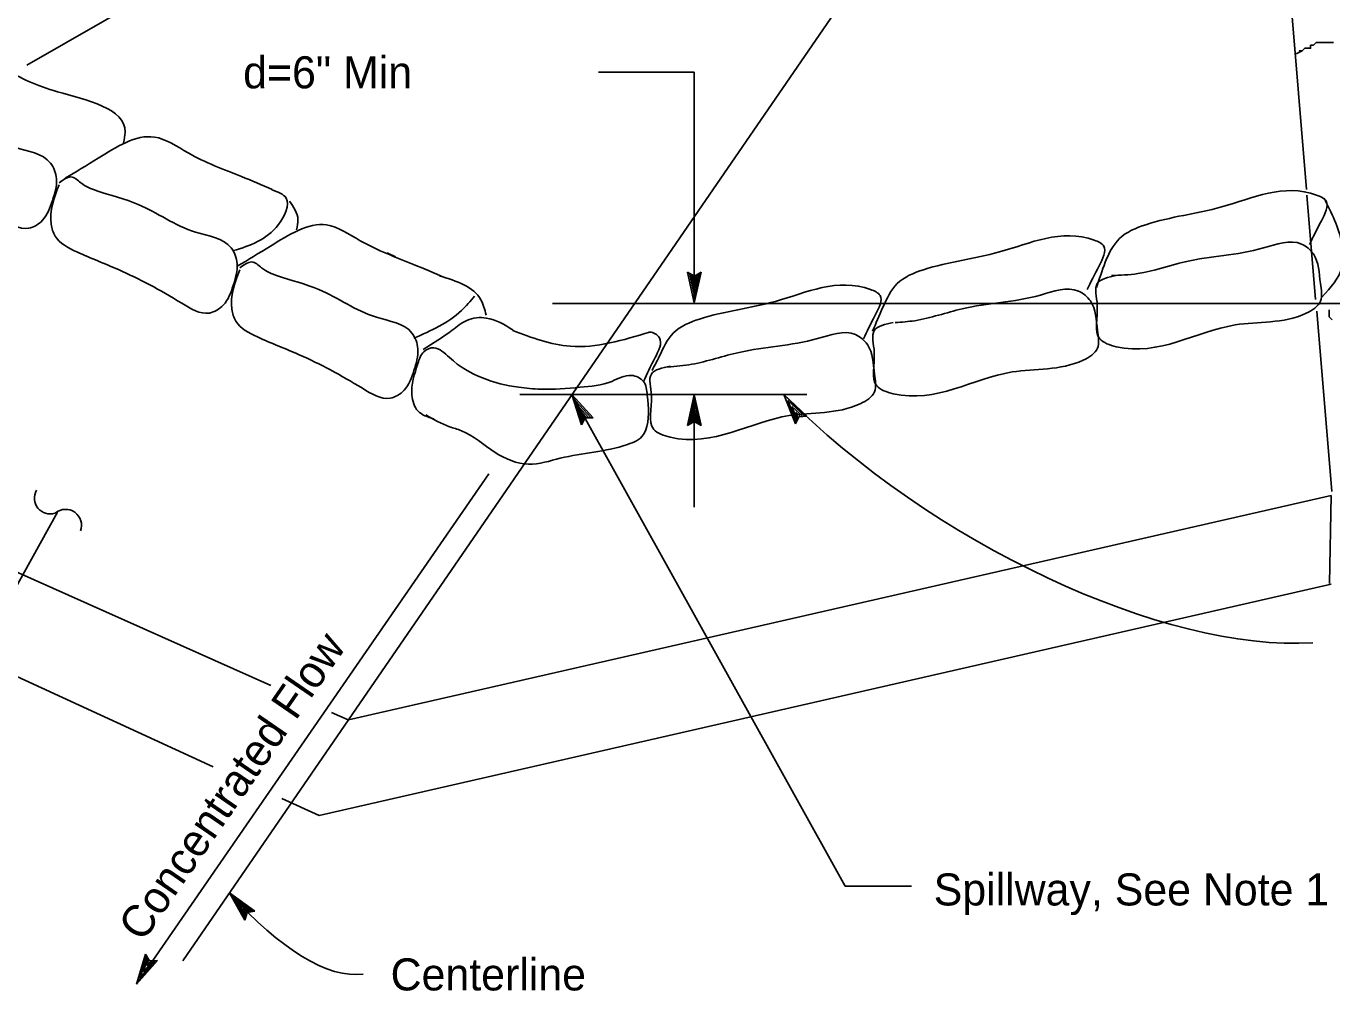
# Model space of a CAD drawing. Extents: x 6707415 to 6708768, y 1869893 to 1870831.
# Drawn here: x 6708364.3 to 6708608.7, y 1870111.8 to 1870292.4 of the extents above; entities that cross this region are included whole.
import ezdxf

# ---------------------------------------------------------------- set-up
doc = ezdxf.new("R2010")
doc.units = 0
for name, color, linetype in [('56 Stg 3 Anno', 7, 'Continuous'), ('57 Undefined', 7, 'Continuous'), ('60 Nongeo Data', 7, 'Continuous')]:
    doc.layers.add(name, color=color, linetype=linetype)

msp = doc.modelspace()

# ---------------------------------------------------------------- linework, layer by layer
at = {"layer": '56 Stg 3 Anno'}
for p, q in [((6708393.6, 1870117.38), (6708574.91, 1870381.27)), ((6708489.35, 1870283.77), (6708471.41, 1870283.77)), ((6708489.35, 1870240.61), (6708489.35, 1870283.77)), ((6708489.35, 1870240.61), (6708488.1, 1870246.37)), ((6708488.1, 1870246.37), (6708488.1, 1870246.37)), ((6708488.1, 1870246.37), (6708489.37, 1870245.6)), ((6708489.36, 1870241.94), (6708488.44, 1870246.15)), ((6708489.37, 1870243.26), (6708488.78, 1870245.98)), ((6708489.37, 1870244.59), (6708489.12, 1870245.75)), ((6708490.66, 1870246.36), (6708489.35, 1870240.61)), ((6708490.32, 1870246.16), (6708489.36, 1870241.93)), ((6708489.37, 1870245.6), (6708490.66, 1870246.36)), ((6708489.97, 1870245.93), (6708489.37, 1870243.26)), ((6708489.64, 1870245.77), (6708489.37, 1870244.59)), ((6708490.66, 1870246.36), (6708490.66, 1870246.36)), ((6708489.35, 1870240.61), (6708489.35, 1870240.61)), ((6708641.41, 1870240.47), (6708462.78, 1870240.47)), ((6708510.4, 1870223.41), (6708456.68, 1870223.41)), ((6708466.45, 1870223.41), (6708517.58, 1870131.35)), ((6708468.21, 1870217.77), (6708466.45, 1870223.41)), ((6708466.45, 1870223.41), (6708466.45, 1870223.41)), ((6708466.45, 1870223.41), (6708470.43, 1870219.05)), ((6708468.4, 1870218.12), (6708467.11, 1870222.26)), ((6708467.12, 1870222.25), (6708470.02, 1870219.08)), ((6708468.59, 1870218.49), (6708467.77, 1870221.11)), ((6708467.77, 1870221.11), (6708469.64, 1870219.06)), ((6708488.06, 1870217.63), (6708489.35, 1870223.39)), ((6708488.4, 1870217.84), (6708489.35, 1870222.07)), ((6708489.35, 1870223.39), (6708489.35, 1870223.39)), ((6708489.35, 1870223.39), (6708490.62, 1870217.63)), ((6708489.35, 1870202.31), (6708489.35, 1870223.39)), ((6708489.36, 1870222.06), (6708490.28, 1870217.86)), ((6708508.31, 1870217.92), (6708506.13, 1870223.41)), ((6708506.13, 1870223.41), (6708506.13, 1870223.41)), ((6708506.13, 1870223.41), (6708510.43, 1870219.36)), ((6708508.47, 1870218.28), (6708506.88, 1870222.31)), ((6708506.89, 1870222.3), (6708510.01, 1870219.35)), ((6708508.63, 1870218.66), (6708507.62, 1870221.21)), ((6708507.62, 1870221.21), (6708509.64, 1870219.3)), ((6708468.94, 1870219.08), (6708468.21, 1870217.77)), ((6708468.79, 1870218.8), (6708468.43, 1870219.96)), ((6708468.43, 1870219.96), (6708469.23, 1870219.08)), ((6708470.43, 1870219.05), (6708468.94, 1870219.08)), ((6708470.43, 1870219.05), (6708470.43, 1870219.05)), ((6708488.75, 1870218.06), (6708489.35, 1870220.74)), ((6708489.08, 1870218.23), (6708489.35, 1870219.41)), ((6708489.35, 1870220.74), (6708489.95, 1870218.03)), ((6708489.35, 1870219.41), (6708489.6, 1870218.25)), ((6708508.94, 1870219.28), (6708508.31, 1870217.92)), ((6708508.81, 1870218.99), (6708508.37, 1870220.11)), ((6708508.37, 1870220.11), (6708509.23, 1870219.3)), ((6708510.43, 1870219.36), (6708508.94, 1870219.28)), ((6708510.43, 1870219.36), (6708510.43, 1870219.36)), ((6708468.21, 1870217.77), (6708468.21, 1870217.77)), ((6708489.35, 1870218.4), (6708488.06, 1870217.63)), ((6708488.06, 1870217.63), (6708488.06, 1870217.63)), ((6708490.62, 1870217.63), (6708489.35, 1870218.4)), ((6708490.62, 1870217.63), (6708490.62, 1870217.63)), ((6708508.31, 1870217.92), (6708508.31, 1870217.92)), ((6708384.97, 1870112.98), (6708450.88, 1870208.6)), ((6708370.17, 1870201.4), (6708341.72, 1870150.18)), ((6708530.03, 1870131.34), (6708517.58, 1870131.35)), ((6708405.21, 1870124.98), (6708402.33, 1870130.13)), ((6708402.33, 1870130.13), (6708402.33, 1870130.13)), ((6708402.33, 1870130.13), (6708407.12, 1870126.68)), ((6708405.33, 1870125.36), (6708403.21, 1870129.14)), ((6708403.23, 1870129.14), (6708406.71, 1870126.62)), ((6708405.43, 1870125.76), (6708404.1, 1870128.15)), ((6708404.1, 1870128.15), (6708406.35, 1870126.53)), ((6708405.57, 1870126.1), (6708404.98, 1870127.16)), ((6708404.98, 1870127.16), (6708405.95, 1870126.47)), ((6708405.66, 1870126.41), (6708405.21, 1870124.98)), ((6708407.12, 1870126.68), (6708405.66, 1870126.41)), ((6708407.12, 1870126.68), (6708407.12, 1870126.68)), ((6708405.21, 1870124.98), (6708405.21, 1870124.98)), ((6708384.97, 1870112.98), (6708386.6, 1870118.65)), ((6708386.6, 1870118.65), (6708386.6, 1870118.65)), ((6708386.6, 1870118.65), (6708387.36, 1870117.37)), ((6708388.85, 1870117.43), (6708384.97, 1870112.98)), ((6708388.45, 1870117.41), (6708385.6, 1870114.14)), ((6708385.61, 1870114.16), (6708386.8, 1870118.29)), ((6708386.24, 1870115.31), (6708387.01, 1870117.98)), ((6708388.04, 1870117.37), (6708386.24, 1870115.31)), ((6708386.87, 1870116.47), (6708387.2, 1870117.62)), ((6708387.67, 1870117.38), (6708386.87, 1870116.47)), ((6708387.36, 1870117.37), (6708388.85, 1870117.43)), ((6708388.85, 1870117.43), (6708388.85, 1870117.43)), ((6708384.97, 1870112.98), (6708384.97, 1870112.98))]:
    msp.add_line(p, q, dxfattribs=at)
for centre, radius, start, end in [((6708368.79, 1870204.02), 2.96, 150.2525, 287.0948), ((6708371.66, 1870198.94), 2.99, 339.2494, 129.7493)]:
    msp.add_arc(centre, radius, start, end, dxfattribs=at)
for centre, major_axis, ratio, start_param, end_param in [((6708556.07, 1870228.58), (68.84, -42.22), 0.434429, 4.196151, 5.732815), ((6708401.15, 1870176.64), (-29.01, 60.95), 0.360833, 2.25187, 3.024453)]:
    msp.add_ellipse(centre, major_axis=major_axis, ratio=ratio, start_param=start_param, end_param=end_param, dxfattribs=at)
at = {"layer": '60 Nongeo Data'}
for p, q in [((6708364.4, 1870285.1), (6708457.05, 1870338.34)), ((6708603.97, 1870261.83), (6708598.97, 1870322.05)), ((6708605.65, 1870241.24), (6708604.03, 1870260.77)), ((6708431.89, 1870249.98), (6708433.44, 1870249.23)), ((6708608.67, 1870205.28), (6708605.86, 1870239.03)), ((6708410.09, 1870168.95), (6708270.51, 1870231.15)), ((6708608.54, 1870204.55), (6708608.26, 1870188.04)), ((6708424.54, 1870162.51), (6708421.47, 1870163.87))]:
    msp.add_line(p, q, dxfattribs=at)
for points in [[(6708602.03, 1870287.23), (6708603.1, 1870287.76), (6708602.57, 1870287.76), (6708603.1, 1870287.76), (6708603.64, 1870288.29), (6708604.17, 1870288.29), (6708604.71, 1870288.29), (6708604.71, 1870288.83), (6708605.24, 1870288.83), (6708605.78, 1870289.36), (6708606.31, 1870289.36), (6708607.38, 1870289.36), (6708608.99, 1870289.36)], [(6708608.74, 1870237.44), (6708608.2, 1870237.98), (6708608.2, 1870238.51), (6708608.2, 1870239.05), (6708608.2, 1870239.26)], [(6708399.28, 1870153.7), (6708268.39, 1870213.92)], [(6708424.62, 1870162.52), (6708608.54, 1870204.55)], [(6708608.53, 1870187.89), (6708419.11, 1870144.57), (6708412.12, 1870147.79)]]:
    msp.add_lwpolyline(points, dxfattribs=at)
for points in [[(6708337.24, 1870279.53), (6708348.66, 1870286.04), (6708353.85, 1870287.52), (6708360.14, 1870284.57), (6708370.14, 1870280.13), (6708382.81, 1870272.53), (6708382.5, 1870270.58)], [(6708336.62, 1870278.61), (6708335.13, 1870271.21), (6708335.88, 1870269), (6708339.95, 1870266.04), (6708347.73, 1870262.71), (6708359.58, 1870256.43), (6708364.76, 1870254.58), (6708367.35, 1870256.06), (6708369.21, 1870259.76), (6708369.95, 1870263.82), (6708368.84, 1870266.78), (6708362.17, 1870269.74), (6708351.43, 1870274.91), (6708343.65, 1870277.5), (6708340.69, 1870278.98), (6708338.84, 1870280.08), (6708337.73, 1870279.71), (6708336.62, 1870278.98)], [(6708371.57, 1870263.92), (6708377.77, 1870267.67), (6708388.3, 1870271.65), (6708394.59, 1870268.69), (6708404.59, 1870264.26), (6708410.34, 1870261.83)], [(6708370.45, 1870262.71), (6708368.97, 1870255.32), (6708369.71, 1870253.1), (6708373.78, 1870250.15), (6708381.56, 1870246.82), (6708393.41, 1870240.54), (6708398.6, 1870238.69), (6708401.19, 1870240.17), (6708403.04, 1870243.86), (6708403.78, 1870247.93), (6708402.67, 1870250.89), (6708396, 1870253.84), (6708385.26, 1870259.02), (6708377.49, 1870261.6), (6708374.52, 1870263.08), (6708372.67, 1870264.19), (6708371.56, 1870263.82), (6708370.45, 1870263.08)], [(6708604.5, 1870251.53), (6708606.72, 1870255.97), (6708607.61, 1870259.66), (6708605.84, 1870260.77), (6708588.06, 1870258.55), (6708573.84, 1870255.23), (6708568.95, 1870252.64), (6708566.28, 1870248.2), (6708564.66, 1870243.47)], [(6708403.11, 1870250.37), (6708411.5, 1870255.25), (6708412.95, 1870260.22), (6708410.26, 1870261.77)], [(6708607.24, 1870260.19), (6708610.57, 1870251.69), (6708610.57, 1870247.25), (6708606.87, 1870241.71)], [(6708413.6, 1870259.63), (6708415.17, 1870256.21), (6708414.87, 1870254.25)], [(6708403.8, 1870247.45), (6708410, 1870251.21), (6708420.53, 1870255.18), (6708426.82, 1870252.23), (6708436.82, 1870247.79), (6708442.57, 1870245.36)], [(6708562.89, 1870243.09), (6708565.11, 1870247.53), (6708566, 1870251.23), (6708564.22, 1870252.33), (6708546.45, 1870250.12), (6708532.23, 1870246.79), (6708527.34, 1870244.2), (6708524.67, 1870239.77), (6708522.69, 1870235.27)], [(6708568.34, 1870245.7), (6708564.78, 1870244.22), (6708564.78, 1870240.15), (6708565.23, 1870233.87), (6708568.34, 1870232.39), (6708590.56, 1870236.46), (6708603.89, 1870238.67), (6708606.55, 1870240.89), (6708606.55, 1870244.22), (6708605.22, 1870249.76), (6708603, 1870251.61), (6708595.89, 1870250.87), (6708581.22, 1870248.28), (6708572.34, 1870246.07), (6708567.45, 1870245.7)], [(6708404.28, 1870246.78), (6708402.8, 1870239.39), (6708403.54, 1870237.17), (6708407.62, 1870234.21), (6708415.39, 1870230.88), (6708427.24, 1870224.6), (6708432.43, 1870222.75), (6708435.02, 1870224.23), (6708436.87, 1870227.93), (6708437.61, 1870231.99), (6708436.5, 1870234.95), (6708429.84, 1870237.91), (6708419.1, 1870243.08), (6708411.32, 1870245.67), (6708408.36, 1870247.15), (6708406.51, 1870248.26), (6708405.39, 1870247.89), (6708404.28, 1870247.15)], [(6708441.68, 1870245.66), (6708449.4, 1870241.18), (6708450.37, 1870238.32)], [(6708521, 1870233.86), (6708523.23, 1870238.3), (6708524.12, 1870241.99), (6708522.34, 1870243.1), (6708504.56, 1870240.88), (6708490.34, 1870237.56), (6708485.45, 1870234.97), (6708482.79, 1870230.54), (6708481.45, 1870227.95)], [(6708526.6, 1870236.89), (6708523.04, 1870235.41), (6708523.04, 1870231.34), (6708523.49, 1870225.06), (6708526.6, 1870223.58), (6708548.82, 1870227.65), (6708562.15, 1870229.87), (6708564.82, 1870232.08), (6708564.82, 1870235.41), (6708563.49, 1870240.95), (6708561.26, 1870242.8), (6708554.15, 1870242.06), (6708539.49, 1870239.48), (6708530.6, 1870237.26), (6708526.97, 1870236.9)], [(6708436.87, 1870233.97), (6708445.76, 1870239.14), (6708448.23, 1870241.87)], [(6708455.44, 1870235.49), (6708450.42, 1870237.76), (6708446.78, 1870237.31), (6708444.05, 1870235.49), (6708438.58, 1870231.85)], [(6708455.37, 1870235.41), (6708466.13, 1870232.47), (6708481, 1870235.13)], [(6708479.87, 1870225.86), (6708482, 1870230.35), (6708482.81, 1870234.06), (6708481.01, 1870235.13), (6708480.85, 1870235.13)], [(6708484.86, 1870228.73), (6708481.31, 1870227.25), (6708481.31, 1870223.19), (6708481.75, 1870216.91), (6708484.86, 1870215.43), (6708507.08, 1870219.49), (6708520.42, 1870221.71), (6708523.08, 1870223.93), (6708523.08, 1870227.25), (6708521.75, 1870232.8), (6708519.53, 1870234.65), (6708512.42, 1870233.91), (6708497.75, 1870231.32), (6708488.86, 1870229.1), (6708484.39, 1870228.54)], [(6708440.57, 1870218.88), (6708437.61, 1870220.36), (6708436.49, 1870223.32), (6708437.61, 1870229.23), (6708438.72, 1870231.45), (6708440.57, 1870232.19), (6708443.53, 1870230.34), (6708456.49, 1870224.79), (6708460.57, 1870224.42), (6708467.97, 1870224.79), (6708473.9, 1870225.9), (6708477.6, 1870227.01), (6708479.82, 1870225.9), (6708480.56, 1870223.32), (6708480.19, 1870216.66), (6708479.82, 1870215.92), (6708476.86, 1870214.08), (6708464.27, 1870211.49), (6708458.34, 1870210.38), (6708452.05, 1870212.6), (6708445.75, 1870216.66), (6708443.53, 1870217.4), (6708439.09, 1870219.62)]]:
    msp.add_spline(points, degree=3, dxfattribs=at)

# ---------------------------------------------------------------- texts
at = {"layer": '57 Undefined'}
for s, p in [('d=6" Min', (6708404.91, 1870280.77)), ('Spillway, See Note 1', (6708534.16, 1870127.75)), ('Centerline', (6708432.51, 1870111.84))]:
    msp.add_text(s, height=6, dxfattribs=at).set_placement(p)
msp.add_text('Concentrated Flow', height=6, rotation=55.457, dxfattribs=at).set_placement((6708386.14, 1870120.7))

doc.saveas('drawing.dxf')
